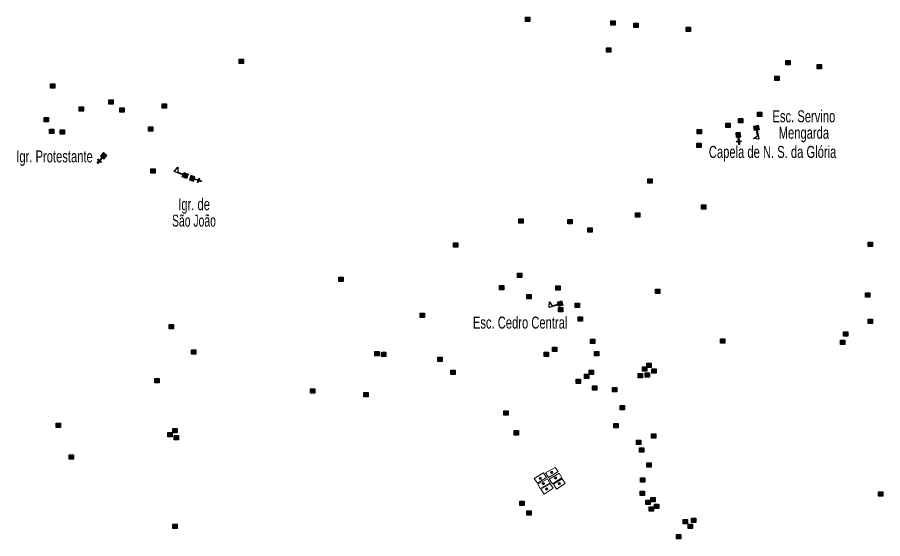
# Model space of a CAD drawing. Extents: x 649.2 to 674.4, y 7040 to 7068.1.
# Drawn here: x 668.26 to 674.05, y 7043.55 to 7047.03 of the extents above; entities that cross this region are included whole.
import ezdxf
from ezdxf.enums import TextEntityAlignment as Align

# ---------------------------------------------------------------- set-up
doc = ezdxf.new("R2010")
doc.units = 0
doc.header["$LTSCALE"] = 0.032
doc.header["$PDMODE"] = 32
doc.header["$PDSIZE"] = 0.016
for name, color, linetype, lineweight in [('2', 7, 'Continuous', 25), ('3', 7, 'Continuous', 13), ('4', 7, 'Continuous', 25), ('6', 7, 'Continuous', 25)]:
    doc.layers.add(name, color=color, linetype=linetype, lineweight=lineweight)
doc.layers.add('61', color=7, linetype='Continuous')

msp = doc.modelspace()

# ---------------------------------------------------------------- hatches: boundary and pattern name
at = {"layer": '2'}
for points in [[(671.664, 7047.0325), (671.693, 7047.0325), (671.693, 7047.0035), (671.664, 7047.0035)], [(672.2365, 7047.0095), (672.2655, 7047.0095), (672.2655, 7046.9805), (672.2365, 7046.9805)], [(672.3887, 7046.9944), (672.4177, 7046.9944), (672.4177, 7046.9654), (672.3887, 7046.9654)], [(672.7396, 7046.9674), (672.7686, 7046.9674), (672.7686, 7046.9384), (672.7396, 7046.9384)], [(672.2064, 7046.8292), (672.2354, 7046.8292), (672.2354, 7046.8002), (672.2064, 7046.8002)], [(669.7488, 7046.7532), (669.7778, 7046.7532), (669.7778, 7046.7242), (669.7488, 7046.7242)], [(673.4061, 7046.7437), (673.4351, 7046.7437), (673.4351, 7046.7147), (673.4061, 7046.7147)], [(673.6175, 7046.7168), (673.6465, 7046.7168), (673.6465, 7046.6878), (673.6175, 7046.6878)], [(673.3323, 7046.6396), (673.3613, 7046.6396), (673.3613, 7046.6106), (673.3323, 7046.6106)], [(668.4857, 7046.5877), (668.5147, 7046.5877), (668.5147, 7046.5587), (668.4857, 7046.5587)], [(668.8748, 7046.4814), (668.9038, 7046.4814), (668.9038, 7046.4524), (668.8748, 7046.4524)], [(669.2326, 7046.4542), (669.2616, 7046.4542), (669.2616, 7046.4252), (669.2326, 7046.4252)], [(668.6762, 7046.4329), (668.7052, 7046.4329), (668.7052, 7046.4039), (668.6762, 7046.4039)], [(668.949, 7046.427), (668.978, 7046.427), (668.978, 7046.398), (668.949, 7046.398)], [(673.2177, 7046.3982), (673.2467, 7046.3982), (673.2467, 7046.3692), (673.2177, 7046.3692)], [(668.4421, 7046.3615), (668.4711, 7046.3615), (668.4711, 7046.3325), (668.4421, 7046.3325)], [(673.0907, 7046.3557), (673.1197, 7046.3557), (673.1197, 7046.3267), (673.0907, 7046.3267)], [(668.4778, 7046.2841), (668.5068, 7046.2841), (668.5068, 7046.2551), (668.4778, 7046.2551)], [(668.5492, 7046.2792), (668.5782, 7046.2792), (668.5782, 7046.2502), (668.5492, 7046.2502)], [(669.1402, 7046.2993), (669.1692, 7046.2993), (669.1692, 7046.2703), (669.1402, 7046.2703)], [(672.8131, 7046.2813), (672.8421, 7046.2813), (672.8421, 7046.2523), (672.8131, 7046.2523)], [(673.0057, 7046.3247), (673.0347, 7046.3247), (673.0347, 7046.2957), (673.0057, 7046.2957)], [(672.8118, 7046.1917), (672.8408, 7046.1917), (672.8408, 7046.1627), (672.8118, 7046.1627)], [(669.1569, 7046.0196), (669.1859, 7046.0196), (669.1859, 7045.9906), (669.1569, 7045.9906)], [(672.4827, 7045.9514), (672.5117, 7045.9514), (672.5117, 7045.9224), (672.4827, 7045.9224)], [(672.8415, 7045.7791), (672.8705, 7045.7791), (672.8705, 7045.7501), (672.8415, 7045.7501)], [(672.4001, 7045.724), (672.4291, 7045.724), (672.4291, 7045.695), (672.4001, 7045.695)], [(671.6199, 7045.6851), (671.6489, 7045.6851), (671.6489, 7045.6561), (671.6199, 7045.6561)], [(671.9469, 7045.6799), (671.9759, 7045.6799), (671.9759, 7045.6509), (671.9469, 7045.6509)], [(672.0822, 7045.6243), (672.1112, 7045.6243), (672.1112, 7045.5953), (672.0822, 7045.5953)], [(671.1822, 7045.5233), (671.2112, 7045.5233), (671.2112, 7045.4943), (671.1822, 7045.4943)], [(673.9585, 7045.5287), (673.9875, 7045.5287), (673.9875, 7045.4997), (673.9585, 7045.4997)], [(670.4149, 7045.295), (670.4439, 7045.295), (670.4439, 7045.266), (670.4149, 7045.266)], [(671.6117, 7045.322), (671.6407, 7045.322), (671.6407, 7045.293), (671.6117, 7045.293)], [(671.4905, 7045.2386), (671.5195, 7045.2386), (671.5195, 7045.2096), (671.4905, 7045.2096)], [(671.8674, 7045.2371), (671.8964, 7045.2371), (671.8964, 7045.2081), (671.8674, 7045.2081)], [(671.6731, 7045.178), (671.7021, 7045.178), (671.7021, 7045.149), (671.6731, 7045.149)], [(672.5348, 7045.215), (672.5638, 7045.215), (672.5638, 7045.186), (672.5348, 7045.186)], [(673.9396, 7045.1892), (673.9686, 7045.1892), (673.9686, 7045.1602), (673.9396, 7045.1602)], [(671.9965, 7045.1206), (672.0255, 7045.1206), (672.0255, 7045.0916), (671.9965, 7045.0916)], [(670.9596, 7045.0539), (670.9886, 7045.0539), (670.9886, 7045.0249), (670.9596, 7045.0249)], [(671.8848, 7045.0907), (671.9138, 7045.0907), (671.9138, 7045.0617), (671.8848, 7045.0617)], [(672.0177, 7045.0293), (672.0467, 7045.0293), (672.0467, 7045.0003), (672.0177, 7045.0003)], [(673.958, 7045.013), (673.987, 7045.013), (673.987, 7044.984), (673.958, 7044.984)], [(669.279, 7044.9781), (669.308, 7044.9781), (669.308, 7044.9491), (669.279, 7044.9491)], [(672.0984, 7044.8793), (672.1274, 7044.8793), (672.1274, 7044.8503), (672.0984, 7044.8503)], [(672.9684, 7044.8818), (672.9974, 7044.8818), (672.9974, 7044.8528), (672.9684, 7044.8528)], [(673.7922, 7044.9278), (673.8212, 7044.9278), (673.8212, 7044.8988), (673.7922, 7044.8988)], [(671.8457, 7044.8257), (671.8747, 7044.8257), (671.8747, 7044.7967), (671.8457, 7044.7967)], [(673.7726, 7044.8725), (673.8016, 7044.8725), (673.8016, 7044.8435), (673.7726, 7044.8435)], [(669.4287, 7044.8074), (669.4577, 7044.8074), (669.4577, 7044.7784), (669.4287, 7044.7784)], [(670.6568, 7044.7971), (670.6858, 7044.7971), (670.6858, 7044.7681), (670.6568, 7044.7681)], [(670.7002, 7044.7928), (670.7292, 7044.7928), (670.7292, 7044.7638), (670.7002, 7044.7638)], [(671.7899, 7044.7925), (671.8189, 7044.7925), (671.8189, 7044.7635), (671.7899, 7044.7635)], [(672.1259, 7044.7974), (672.1549, 7044.7974), (672.1549, 7044.7684), (672.1259, 7044.7684)], [(671.0786, 7044.7588), (671.1076, 7044.7588), (671.1076, 7044.7298), (671.0786, 7044.7298)], [(672.4774, 7044.72), (672.5064, 7044.72), (672.5064, 7044.691), (672.4774, 7044.691)], [(671.1654, 7044.6729), (671.1944, 7044.6729), (671.1944, 7044.6439), (671.1654, 7044.6439)], [(672.0913, 7044.6732), (672.1203, 7044.6732), (672.1203, 7044.6442), (672.0913, 7044.6442)], [(672.4174, 7044.6502), (672.4464, 7044.6502), (672.4464, 7044.6212), (672.4174, 7044.6212)], [(672.4477, 7044.6942), (672.4767, 7044.6942), (672.4767, 7044.6652), (672.4477, 7044.6652)], [(672.4642, 7044.654), (672.4932, 7044.654), (672.4932, 7044.625), (672.4642, 7044.625)], [(672.5092, 7044.6821), (672.5382, 7044.6821), (672.5382, 7044.6531), (672.5092, 7044.6531)], [(669.1832, 7044.6158), (669.2122, 7044.6158), (669.2122, 7044.5868), (669.1832, 7044.5868)], [(672.0038, 7044.6118), (672.0328, 7044.6118), (672.0328, 7044.5828), (672.0038, 7044.5828)], [(672.0596, 7044.6457), (672.0886, 7044.6457), (672.0886, 7044.6167), (672.0596, 7044.6167)], [(670.2252, 7044.5466), (670.2542, 7044.5466), (670.2542, 7044.5176), (670.2252, 7044.5176)], [(672.1139, 7044.5673), (672.1429, 7044.5673), (672.1429, 7044.5383), (672.1139, 7044.5383)], [(672.2459, 7044.5567), (672.2749, 7044.5567), (672.2749, 7044.5277), (672.2459, 7044.5277)], [(670.5829, 7044.5229), (670.6119, 7044.5229), (670.6119, 7044.4939), (670.5829, 7044.4939)], [(672.2975, 7044.4365), (672.3265, 7044.4365), (672.3265, 7044.4075), (672.2975, 7044.4075)], [(671.5205, 7044.4005), (671.5495, 7044.4005), (671.5495, 7044.3715), (671.5205, 7044.3715)], [(668.5222, 7044.3185), (668.5512, 7044.3185), (668.5512, 7044.2895), (668.5222, 7044.2895)], [(672.2547, 7044.3159), (672.2837, 7044.3159), (672.2837, 7044.2869), (672.2547, 7044.2869)], [(669.2702, 7044.2553), (669.2992, 7044.2553), (669.2992, 7044.2263), (669.2702, 7044.2263)], [(669.3051, 7044.2832), (669.3341, 7044.2832), (669.3341, 7044.2542), (669.3051, 7044.2542)], [(671.5877, 7044.2677), (671.6167, 7044.2677), (671.6167, 7044.2387), (671.5877, 7044.2387)], [(672.5084, 7044.246), (672.5374, 7044.246), (672.5374, 7044.217), (672.5084, 7044.217)], [(669.3138, 7044.2344), (669.3428, 7044.2344), (669.3428, 7044.2054), (669.3138, 7044.2054)], [(672.4064, 7044.2032), (672.4354, 7044.2032), (672.4354, 7044.1742), (672.4064, 7044.1742)], [(672.4278, 7044.1536), (672.4568, 7044.1536), (672.4568, 7044.1246), (672.4278, 7044.1246)], [(668.6097, 7044.1053), (668.6387, 7044.1053), (668.6387, 7044.0763), (668.6097, 7044.0763)], [(672.4773, 7044.0525), (672.5063, 7044.0525), (672.5063, 7044.0235), (672.4773, 7044.0235)], [(672.4344, 7043.9526), (672.4634, 7043.9526), (672.4634, 7043.9236), (672.4344, 7043.9236)], [(672.4317, 7043.8639), (672.4607, 7043.8639), (672.4607, 7043.8349), (672.4317, 7043.8349)], [(674.026, 7043.8576), (674.055, 7043.8576), (674.055, 7043.8286), (674.026, 7043.8286)], [(671.6267, 7043.7971), (671.6557, 7043.7971), (671.6557, 7043.7681), (671.6267, 7043.7681)], [(672.4693, 7043.802), (672.4983, 7043.802), (672.4983, 7043.773), (672.4693, 7043.773)], [(672.5025, 7043.8199), (672.5315, 7043.8199), (672.5315, 7043.7909), (672.5025, 7043.7909)], [(671.673, 7043.7314), (671.702, 7043.7314), (671.702, 7043.7024), (671.673, 7043.7024)], [(672.4927, 7043.7589), (672.5217, 7043.7589), (672.5217, 7043.7299), (672.4927, 7043.7299)], [(672.5285, 7043.7769), (672.5575, 7043.7769), (672.5575, 7043.7479), (672.5285, 7043.7479)], [(672.7195, 7043.6746), (672.7485, 7043.6746), (672.7485, 7043.6456), (672.7195, 7043.6456)], [(672.776, 7043.6827), (672.805, 7043.6827), (672.805, 7043.6537), (672.776, 7043.6537)], [(669.3052, 7043.6421), (669.3342, 7043.6421), (669.3342, 7043.6131), (669.3052, 7043.6131)], [(672.7527, 7043.6423), (672.7817, 7043.6423), (672.7817, 7043.6133), (672.7527, 7043.6133)], [(672.6747, 7043.5742), (672.7037, 7043.5742), (672.7037, 7043.5452), (672.6747, 7043.5452)]]:
    msp.add_hatch(color=256, dxfattribs=at).paths.add_polyline_path(points)
at = {"layer": '4'}
for points in [[(673.2215, 7046.3105), (673.2272, 7046.281), (673.1978, 7046.2753), (673.192, 7046.3047)], [(669.3951, 7045.9555), (669.3672, 7045.9665), (669.3783, 7045.9944), (669.4062, 7045.9834)], [(671.9151, 7045.107), (671.8864, 7045.0981), (671.8775, 7045.1268), (671.9062, 7045.1357)]]:
    msp.add_hatch(color=256, dxfattribs=at).paths.add_polyline_path(points)
at = {"layer": '6'}
for points in [[(673.1051, 7046.2333), (673.1022, 7046.2631), (673.0724, 7046.2603), (673.0752, 7046.2305)], [(673.0876, 7046.2316), (673.0926, 7046.2321), (673.0952, 7046.2047), (673.1076, 7046.2059), (673.1081, 7046.2009), (673.0957, 7046.1998), (673.0973, 7046.1823), (673.0923, 7046.1819), (673.0907, 7046.1993), (673.0783, 7046.1981), (673.0778, 7046.2031), (673.0902, 7046.2043)], [(668.8302, 7046.0972), (668.8341, 7046.0939), (668.8163, 7046.0729), (668.8259, 7046.0649), (668.8226, 7046.0611), (668.8131, 7046.0691), (668.8018, 7046.0558), (668.7979, 7046.059), (668.8093, 7046.0724), (668.7997, 7046.0804), (668.803, 7046.0842), (668.8125, 7046.0762)], [(668.8436, 7046.0859), (668.863, 7046.1088), (668.8401, 7046.1281), (668.8208, 7046.1052)], [(669.4523, 7045.965), (669.4237, 7045.9741), (669.4146, 7045.9455), (669.4432, 7045.9364)], [(669.447, 7045.9483), (669.4485, 7045.9531), (669.4747, 7045.9448), (669.4785, 7045.9567), (669.4833, 7045.9552), (669.4795, 7045.9432), (669.4962, 7045.938), (669.4947, 7045.9332), (669.478, 7045.9385), (669.4742, 7045.9266), (669.4694, 7045.9281), (669.4732, 7045.94)]]:
    msp.add_hatch(color=256, dxfattribs=at).paths.add_polyline_path(points)

# ---------------------------------------------------------------- linework, layer by layer
at = {"layer": '2'}
for points in [[(671.664, 7047.0325), (671.693, 7047.0325), (671.693, 7047.0035), (671.664, 7047.0035)], [(672.2365, 7047.0095), (672.2655, 7047.0095), (672.2655, 7046.9805), (672.2365, 7046.9805)], [(672.3887, 7046.9944), (672.4177, 7046.9944), (672.4177, 7046.9654), (672.3887, 7046.9654)], [(672.7396, 7046.9674), (672.7686, 7046.9674), (672.7686, 7046.9384), (672.7396, 7046.9384)], [(672.2064, 7046.8292), (672.2354, 7046.8292), (672.2354, 7046.8002), (672.2064, 7046.8002)], [(669.7488, 7046.7532), (669.7778, 7046.7532), (669.7778, 7046.7242), (669.7488, 7046.7242)], [(673.4061, 7046.7437), (673.4351, 7046.7437), (673.4351, 7046.7147), (673.4061, 7046.7147)], [(673.6175, 7046.7168), (673.6465, 7046.7168), (673.6465, 7046.6878), (673.6175, 7046.6878)], [(673.3323, 7046.6396), (673.3613, 7046.6396), (673.3613, 7046.6106), (673.3323, 7046.6106)], [(668.4857, 7046.5877), (668.5147, 7046.5877), (668.5147, 7046.5587), (668.4857, 7046.5587)], [(668.8748, 7046.4814), (668.9038, 7046.4814), (668.9038, 7046.4524), (668.8748, 7046.4524)], [(669.2326, 7046.4542), (669.2616, 7046.4542), (669.2616, 7046.4252), (669.2326, 7046.4252)], [(668.6762, 7046.4329), (668.7052, 7046.4329), (668.7052, 7046.4039), (668.6762, 7046.4039)], [(668.949, 7046.427), (668.978, 7046.427), (668.978, 7046.398), (668.949, 7046.398)], [(673.2177, 7046.3982), (673.2467, 7046.3982), (673.2467, 7046.3692), (673.2177, 7046.3692)], [(668.4421, 7046.3615), (668.4711, 7046.3615), (668.4711, 7046.3325), (668.4421, 7046.3325)], [(673.0907, 7046.3557), (673.1197, 7046.3557), (673.1197, 7046.3267), (673.0907, 7046.3267)], [(668.4778, 7046.2841), (668.5068, 7046.2841), (668.5068, 7046.2551), (668.4778, 7046.2551)], [(668.5492, 7046.2792), (668.5782, 7046.2792), (668.5782, 7046.2502), (668.5492, 7046.2502)], [(669.1402, 7046.2993), (669.1692, 7046.2993), (669.1692, 7046.2703), (669.1402, 7046.2703)], [(672.8131, 7046.2813), (672.8421, 7046.2813), (672.8421, 7046.2523), (672.8131, 7046.2523)], [(673.0057, 7046.3247), (673.0347, 7046.3247), (673.0347, 7046.2957), (673.0057, 7046.2957)], [(672.8118, 7046.1917), (672.8408, 7046.1917), (672.8408, 7046.1627), (672.8118, 7046.1627)], [(669.1569, 7046.0196), (669.1859, 7046.0196), (669.1859, 7045.9906), (669.1569, 7045.9906)], [(672.4827, 7045.9514), (672.5117, 7045.9514), (672.5117, 7045.9224), (672.4827, 7045.9224)], [(672.8415, 7045.7791), (672.8705, 7045.7791), (672.8705, 7045.7501), (672.8415, 7045.7501)], [(672.4001, 7045.724), (672.4291, 7045.724), (672.4291, 7045.695), (672.4001, 7045.695)], [(671.6199, 7045.6851), (671.6489, 7045.6851), (671.6489, 7045.6561), (671.6199, 7045.6561)], [(671.9469, 7045.6799), (671.9759, 7045.6799), (671.9759, 7045.6509), (671.9469, 7045.6509)], [(672.0822, 7045.6243), (672.1112, 7045.6243), (672.1112, 7045.5953), (672.0822, 7045.5953)], [(671.1822, 7045.5233), (671.2112, 7045.5233), (671.2112, 7045.4943), (671.1822, 7045.4943)], [(673.9585, 7045.5287), (673.9875, 7045.5287), (673.9875, 7045.4997), (673.9585, 7045.4997)], [(670.4149, 7045.295), (670.4439, 7045.295), (670.4439, 7045.266), (670.4149, 7045.266)], [(671.6117, 7045.322), (671.6407, 7045.322), (671.6407, 7045.293), (671.6117, 7045.293)], [(671.4905, 7045.2386), (671.5195, 7045.2386), (671.5195, 7045.2096), (671.4905, 7045.2096)], [(671.8674, 7045.2371), (671.8964, 7045.2371), (671.8964, 7045.2081), (671.8674, 7045.2081)], [(671.6731, 7045.178), (671.7021, 7045.178), (671.7021, 7045.149), (671.6731, 7045.149)], [(672.5348, 7045.215), (672.5638, 7045.215), (672.5638, 7045.186), (672.5348, 7045.186)], [(673.9396, 7045.1892), (673.9686, 7045.1892), (673.9686, 7045.1602), (673.9396, 7045.1602)], [(671.9965, 7045.1206), (672.0255, 7045.1206), (672.0255, 7045.0916), (671.9965, 7045.0916)], [(670.9596, 7045.0539), (670.9886, 7045.0539), (670.9886, 7045.0249), (670.9596, 7045.0249)], [(671.8848, 7045.0907), (671.9138, 7045.0907), (671.9138, 7045.0617), (671.8848, 7045.0617)], [(672.0177, 7045.0293), (672.0467, 7045.0293), (672.0467, 7045.0003), (672.0177, 7045.0003)], [(673.958, 7045.013), (673.987, 7045.013), (673.987, 7044.984), (673.958, 7044.984)], [(669.279, 7044.9781), (669.308, 7044.9781), (669.308, 7044.9491), (669.279, 7044.9491)], [(672.0984, 7044.8793), (672.1274, 7044.8793), (672.1274, 7044.8503), (672.0984, 7044.8503)], [(672.9684, 7044.8818), (672.9974, 7044.8818), (672.9974, 7044.8528), (672.9684, 7044.8528)], [(673.7922, 7044.9278), (673.8212, 7044.9278), (673.8212, 7044.8988), (673.7922, 7044.8988)], [(671.8457, 7044.8257), (671.8747, 7044.8257), (671.8747, 7044.7967), (671.8457, 7044.7967)], [(673.7726, 7044.8725), (673.8016, 7044.8725), (673.8016, 7044.8435), (673.7726, 7044.8435)], [(669.4287, 7044.8074), (669.4577, 7044.8074), (669.4577, 7044.7784), (669.4287, 7044.7784)], [(670.6568, 7044.7971), (670.6858, 7044.7971), (670.6858, 7044.7681), (670.6568, 7044.7681)], [(670.7002, 7044.7928), (670.7292, 7044.7928), (670.7292, 7044.7638), (670.7002, 7044.7638)], [(671.7899, 7044.7925), (671.8189, 7044.7925), (671.8189, 7044.7635), (671.7899, 7044.7635)], [(672.1259, 7044.7974), (672.1549, 7044.7974), (672.1549, 7044.7684), (672.1259, 7044.7684)], [(671.0786, 7044.7588), (671.1076, 7044.7588), (671.1076, 7044.7298), (671.0786, 7044.7298)], [(672.4774, 7044.72), (672.5064, 7044.72), (672.5064, 7044.691), (672.4774, 7044.691)], [(671.1654, 7044.6729), (671.1944, 7044.6729), (671.1944, 7044.6439), (671.1654, 7044.6439)], [(672.0913, 7044.6732), (672.1203, 7044.6732), (672.1203, 7044.6442), (672.0913, 7044.6442)], [(672.4174, 7044.6502), (672.4464, 7044.6502), (672.4464, 7044.6212), (672.4174, 7044.6212)], [(672.4477, 7044.6942), (672.4767, 7044.6942), (672.4767, 7044.6652), (672.4477, 7044.6652)], [(672.4642, 7044.654), (672.4932, 7044.654), (672.4932, 7044.625), (672.4642, 7044.625)], [(672.5092, 7044.6821), (672.5382, 7044.6821), (672.5382, 7044.6531), (672.5092, 7044.6531)], [(669.1832, 7044.6158), (669.2122, 7044.6158), (669.2122, 7044.5868), (669.1832, 7044.5868)], [(672.0038, 7044.6118), (672.0328, 7044.6118), (672.0328, 7044.5828), (672.0038, 7044.5828)], [(672.0596, 7044.6457), (672.0886, 7044.6457), (672.0886, 7044.6167), (672.0596, 7044.6167)], [(670.2252, 7044.5466), (670.2542, 7044.5466), (670.2542, 7044.5176), (670.2252, 7044.5176)], [(672.1139, 7044.5673), (672.1429, 7044.5673), (672.1429, 7044.5383), (672.1139, 7044.5383)], [(672.2459, 7044.5567), (672.2749, 7044.5567), (672.2749, 7044.5277), (672.2459, 7044.5277)], [(670.5829, 7044.5229), (670.6119, 7044.5229), (670.6119, 7044.4939), (670.5829, 7044.4939)], [(672.2975, 7044.4365), (672.3265, 7044.4365), (672.3265, 7044.4075), (672.2975, 7044.4075)], [(671.5205, 7044.4005), (671.5495, 7044.4005), (671.5495, 7044.3715), (671.5205, 7044.3715)], [(668.5222, 7044.3185), (668.5512, 7044.3185), (668.5512, 7044.2895), (668.5222, 7044.2895)], [(672.2547, 7044.3159), (672.2837, 7044.3159), (672.2837, 7044.2869), (672.2547, 7044.2869)], [(669.2702, 7044.2553), (669.2992, 7044.2553), (669.2992, 7044.2263), (669.2702, 7044.2263)], [(669.3051, 7044.2832), (669.3341, 7044.2832), (669.3341, 7044.2542), (669.3051, 7044.2542)], [(671.5877, 7044.2677), (671.6167, 7044.2677), (671.6167, 7044.2387), (671.5877, 7044.2387)], [(672.5084, 7044.246), (672.5374, 7044.246), (672.5374, 7044.217), (672.5084, 7044.217)], [(669.3138, 7044.2344), (669.3428, 7044.2344), (669.3428, 7044.2054), (669.3138, 7044.2054)], [(672.4064, 7044.2032), (672.4354, 7044.2032), (672.4354, 7044.1742), (672.4064, 7044.1742)], [(672.4278, 7044.1536), (672.4568, 7044.1536), (672.4568, 7044.1246), (672.4278, 7044.1246)], [(668.6097, 7044.1053), (668.6387, 7044.1053), (668.6387, 7044.0763), (668.6097, 7044.0763)], [(672.4773, 7044.0525), (672.5063, 7044.0525), (672.5063, 7044.0235), (672.4773, 7044.0235)], [(672.4344, 7043.9526), (672.4634, 7043.9526), (672.4634, 7043.9236), (672.4344, 7043.9236)], [(672.4317, 7043.8639), (672.4607, 7043.8639), (672.4607, 7043.8349), (672.4317, 7043.8349)], [(674.026, 7043.8576), (674.055, 7043.8576), (674.055, 7043.8286), (674.026, 7043.8286)], [(671.6267, 7043.7971), (671.6557, 7043.7971), (671.6557, 7043.7681), (671.6267, 7043.7681)], [(672.4693, 7043.802), (672.4983, 7043.802), (672.4983, 7043.773), (672.4693, 7043.773)], [(672.5025, 7043.8199), (672.5315, 7043.8199), (672.5315, 7043.7909), (672.5025, 7043.7909)], [(671.673, 7043.7314), (671.702, 7043.7314), (671.702, 7043.7024), (671.673, 7043.7024)], [(672.4927, 7043.7589), (672.5217, 7043.7589), (672.5217, 7043.7299), (672.4927, 7043.7299)], [(672.5285, 7043.7769), (672.5575, 7043.7769), (672.5575, 7043.7479), (672.5285, 7043.7479)], [(672.7195, 7043.6746), (672.7485, 7043.6746), (672.7485, 7043.6456), (672.7195, 7043.6456)], [(672.776, 7043.6827), (672.805, 7043.6827), (672.805, 7043.6537), (672.776, 7043.6537)], [(669.3052, 7043.6421), (669.3342, 7043.6421), (669.3342, 7043.6131), (669.3052, 7043.6131)], [(672.7527, 7043.6423), (672.7817, 7043.6423), (672.7817, 7043.6133), (672.7527, 7043.6133)], [(672.6747, 7043.5742), (672.7037, 7043.5742), (672.7037, 7043.5452), (672.6747, 7043.5452)]]:
    msp.add_lwpolyline(points, close=True, dxfattribs=at)
at = {"layer": '3'}
for points in [[(671.7983, 7043.9858), (671.8191, 7043.9552), (671.8832, 7043.9951), (671.8635, 7044.0217)], [(671.7456, 7043.917), (671.806, 7043.9548), (671.7843, 7043.9862), (671.7227, 7043.948)], [(671.823, 7043.9434), (671.845, 7043.9119), (671.9079, 7043.9531), (671.8888, 7043.9832)], [(671.812, 7043.9448), (671.7461, 7043.9106), (671.7635, 7043.8804), (671.8272, 7043.917)], [(671.8285, 7043.9127), (671.8493, 7043.8838), (671.7901, 7043.8424), (671.766, 7043.8754)], [(671.8514, 7043.9089), (671.8726, 7043.8771), (671.9295, 7043.9132), (671.9104, 7043.9463)]]:
    msp.add_lwpolyline(points, close=True, dxfattribs=at)
for p in [(671.7638, 7043.9496), (671.8403, 7043.9885), (671.8657, 7043.9502), (671.7841, 7043.9131), (671.8904, 7043.9125), (671.806, 7043.8782)]:
    msp.add_point(p, dxfattribs=at)
at = {"layer": '4'}
for p, q in [((673.215, 7046.2786), (673.21, 7046.2777)), ((669.3718, 7045.9781), (669.3737, 7045.9828)), ((671.8827, 7045.11), (671.8812, 7045.1148))]:
    msp.add_line(p, q, dxfattribs=at)
for points in [[(673.215, 7046.2786), (673.2269, 7046.2173), (673.1902, 7046.2229), (673.2176, 7046.2389), (673.21, 7046.2777)], [(673.2215, 7046.3105), (673.2272, 7046.281), (673.1978, 7046.2753), (673.192, 7046.3047)], [(669.3718, 7045.9781), (669.3137, 7046.0011), (669.3382, 7046.0291), (669.3369, 7045.9973), (669.3737, 7045.9828)], [(669.3951, 7045.9555), (669.3672, 7045.9665), (669.3783, 7045.9944), (669.4062, 7045.9834)], [(671.8827, 7045.11), (671.823, 7045.0915), (671.8246, 7045.1286), (671.8435, 7045.1031), (671.8812, 7045.1148)], [(671.9151, 7045.107), (671.8864, 7045.0981), (671.8775, 7045.1268), (671.9062, 7045.1357)]]:
    msp.add_lwpolyline(points, close=True, dxfattribs=at)
at = {"layer": '6'}
for points in [[(673.1051, 7046.2333), (673.1022, 7046.2631), (673.0724, 7046.2603), (673.0752, 7046.2305)], [(673.0876, 7046.2316), (673.0926, 7046.2321), (673.0952, 7046.2047), (673.1076, 7046.2059), (673.1081, 7046.2009), (673.0957, 7046.1998), (673.0973, 7046.1823), (673.0923, 7046.1819), (673.0907, 7046.1993), (673.0783, 7046.1981), (673.0778, 7046.2031), (673.0902, 7046.2043)], [(668.8302, 7046.0972), (668.8341, 7046.0939), (668.8163, 7046.0729), (668.8259, 7046.0649), (668.8226, 7046.0611), (668.8131, 7046.0691), (668.8018, 7046.0558), (668.7979, 7046.059), (668.8093, 7046.0724), (668.7997, 7046.0804), (668.803, 7046.0842), (668.8125, 7046.0762)], [(668.8436, 7046.0859), (668.863, 7046.1088), (668.8401, 7046.1281), (668.8208, 7046.1052)], [(669.4523, 7045.965), (669.4237, 7045.9741), (669.4146, 7045.9455), (669.4432, 7045.9364)], [(669.447, 7045.9483), (669.4485, 7045.9531), (669.4747, 7045.9448), (669.4785, 7045.9567), (669.4833, 7045.9552), (669.4795, 7045.9432), (669.4962, 7045.938), (669.4947, 7045.9332), (669.478, 7045.9385), (669.4742, 7045.9266), (669.4694, 7045.9281), (669.4732, 7045.94)]]:
    msp.add_lwpolyline(points, close=True, dxfattribs=at)

# ---------------------------------------------------------------- texts
at = {"layer": '61'}
for s, width, p in [('Esc. Servino', 0.7, (673.3173, 7046.3303)), ('  Mengarda', 0.7, (673.3173, 7046.2203)), ('Capela de N. S. da Glória', 0.7, (672.8914, 7046.0921)), ('  Igr. de ', 0.7, (669.2987, 7045.7424)), ('São João', 0.65, (669.2987, 7045.6324))]:
    msp.add_text(s, height=0.08, dxfattribs=dict(at, width=width)).set_placement(p)
at = {"layer": '61', "width": 0.7}
for s, p in [('Igr. Protestante', (668.7683, 7046.0624)), ('Esc. Cedro Central', (671.9448, 7044.9506))]:
    msp.add_text(s, height=0.08, dxfattribs=at).set_placement(p, align=Align.RIGHT)

doc.saveas('drawing.dxf')
